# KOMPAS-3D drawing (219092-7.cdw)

Referenced files: Вузол стріли.cdw
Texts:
  Курсова робота
  Вузол стріли
  Бабіч
  Текст на чертеже
  Размерные надписи
  Шероховатость
  Линия-выноска #1
  Линия-выноска #2
  Линия-выноска #3
  Отклонения формы и база
  Заголовок таблицы
  Ячейка таблицы
  Стрелка вида
  Обозначение изменения
  Фигурная скобка
  Номер узла
  Марка координационной оси
  VRCB
  Выносная надпись
  Обозначение узла
  Марка/позиционное обозначение с линией-выноской
  Марка/позиционное обозначение на линии
  Марка/позиционное обозначение без линии-выноски
  ГОСТ 5264-80-С1- 3
  ГОСТ 5264-80-У1- 3
  ГОСТ 5264-80-Т1- 3
  ГОСТ 5264-80-Н1- 3
  Горбатюк
  Курсова робота-
Dimensions and other numbers on the sheet: 7; 150; 2N3; 2N1; 2N2; 1:5; 1; 0; 2; 3; 4; 5; 6; 8; 9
